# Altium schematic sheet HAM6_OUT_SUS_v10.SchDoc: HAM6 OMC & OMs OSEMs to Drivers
size C; Engineer: L. Sanchez; Organization: LIGO Laboratory; Address1: California Institute of Technology; Address2: Massachusetts Institute of Technology; DocumentNumber: D1002740; Revision: v10; SheetNumber: 4; SheetTotal: 8
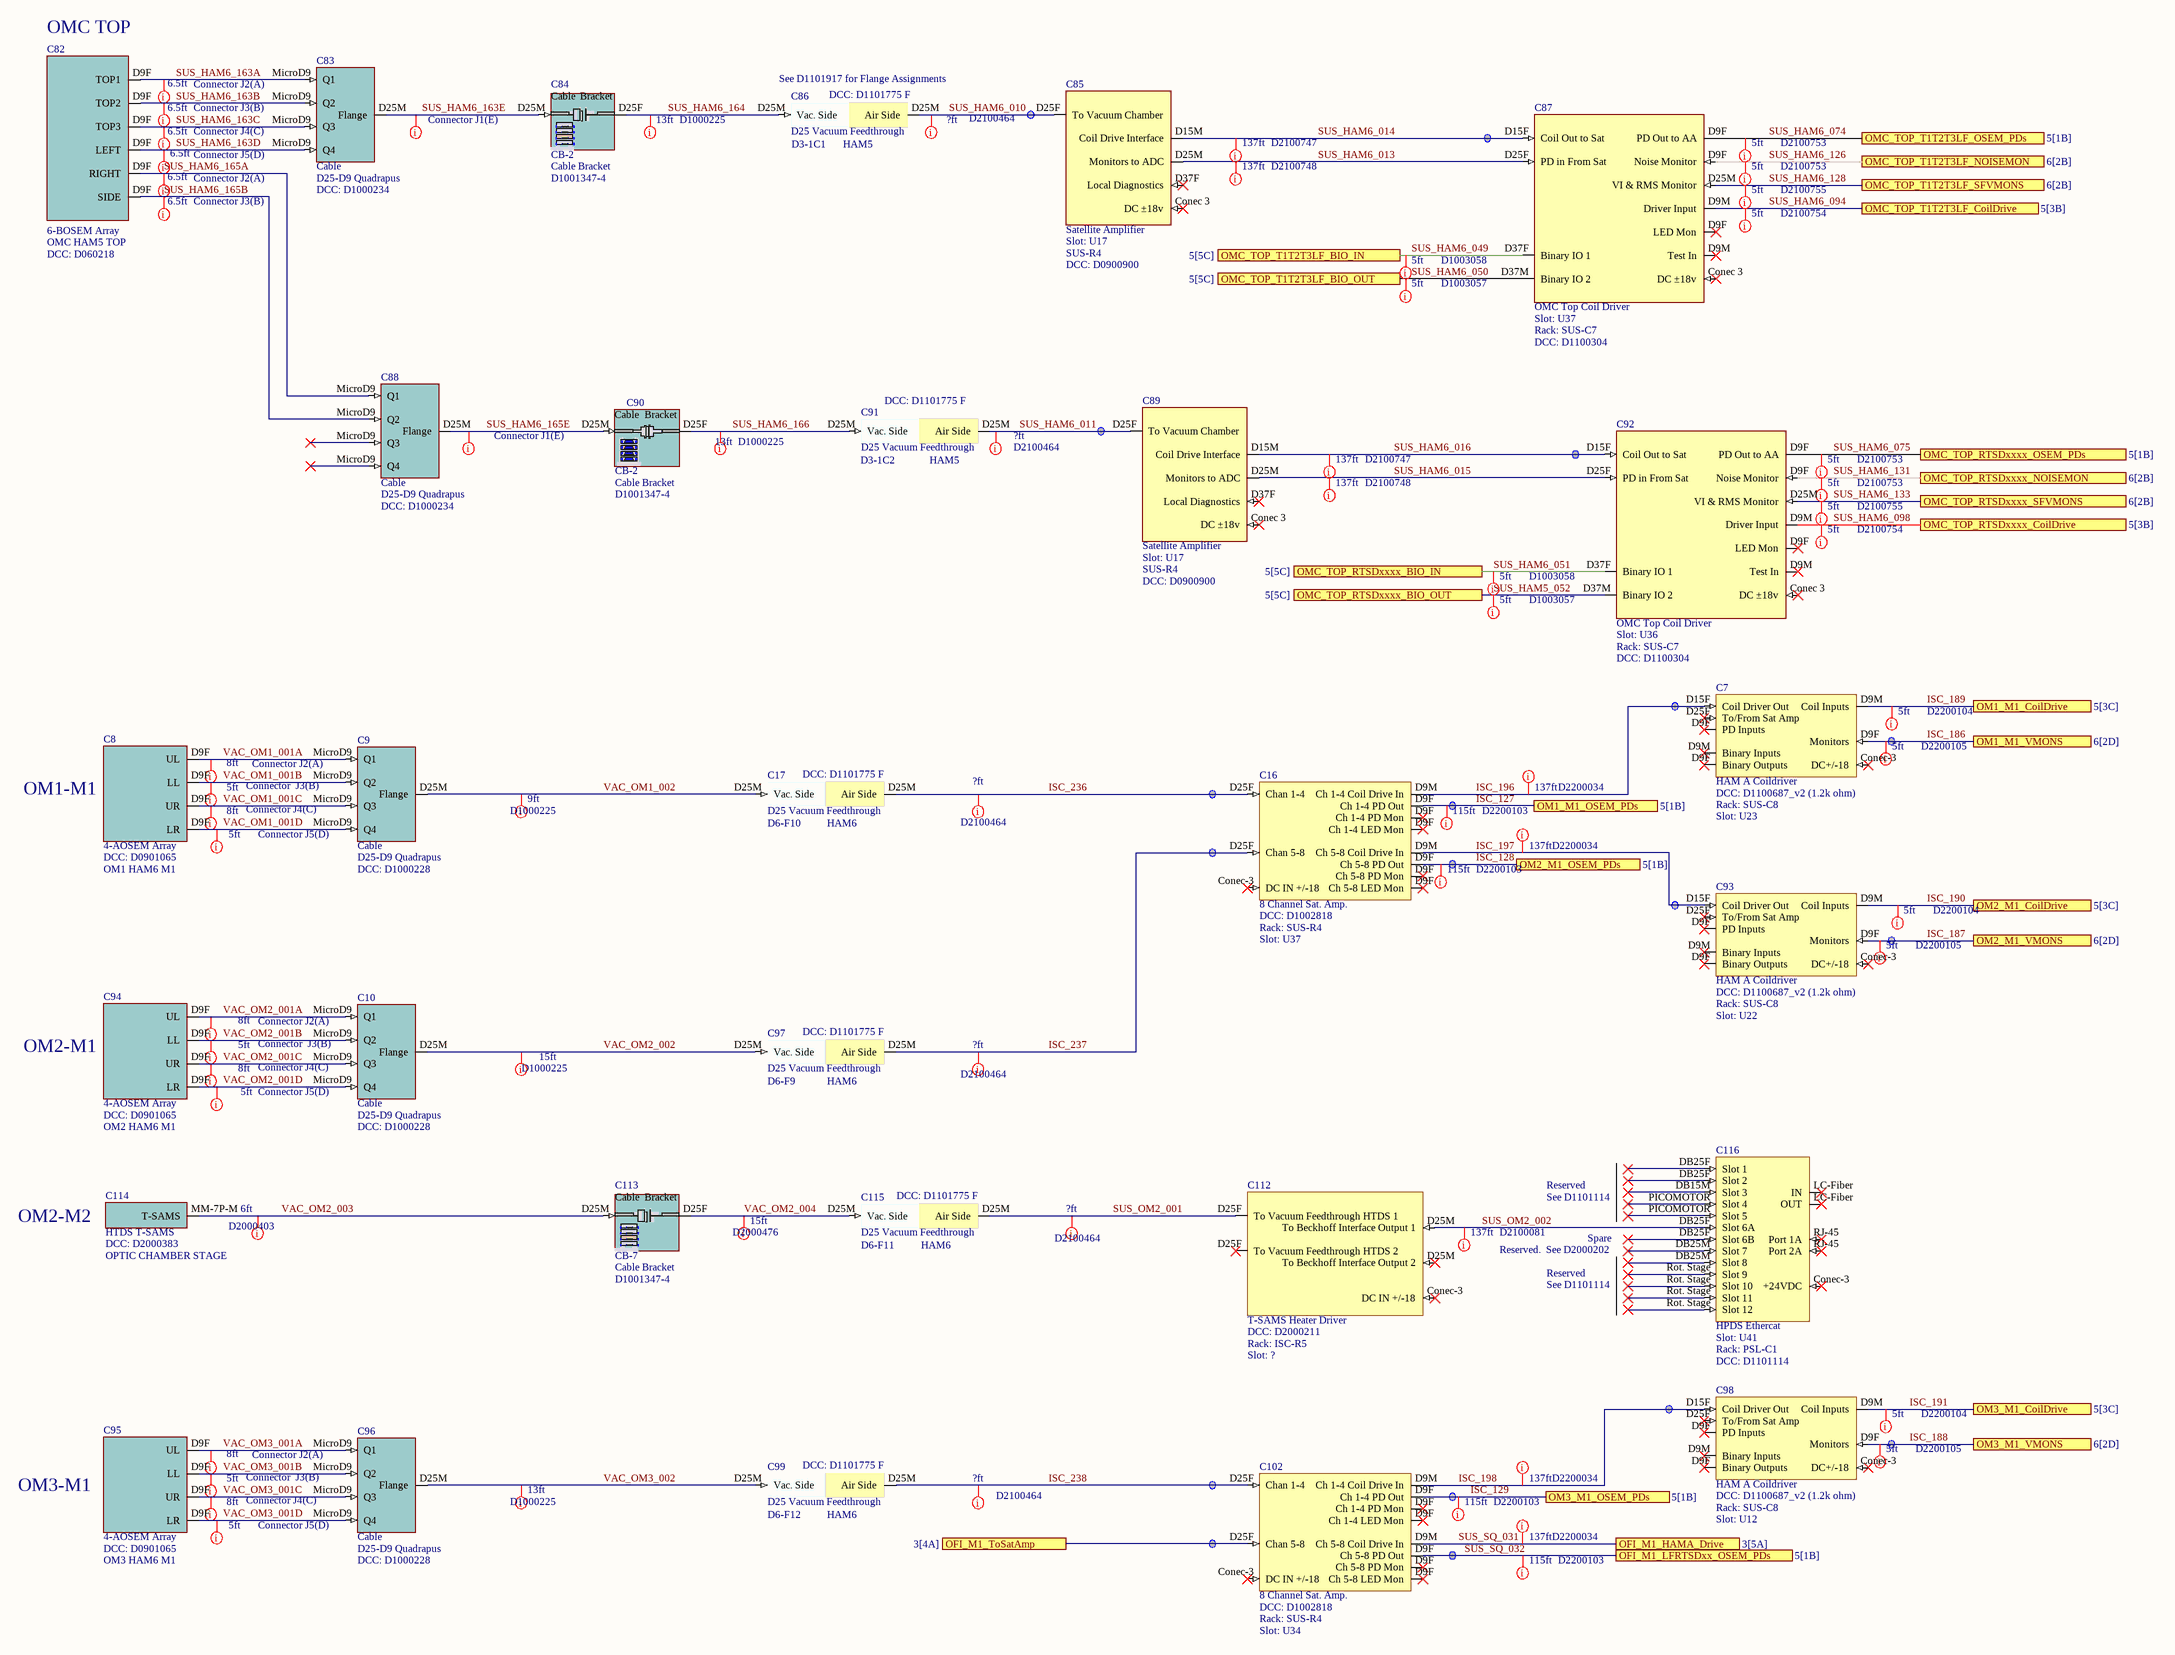
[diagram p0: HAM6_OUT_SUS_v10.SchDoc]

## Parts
C7  HAM A Coildriver  DCC: D1100687_v2 (1.2k ohm)  Rack: SUS-C8  Slot: U23
C8  4-AOSEM Array  DCC: D0901065  Parameter: OM1 HAM6 M1
C9  Cable  value D25-D9 Quadrapus  DCC: D1000228
C10  Cable  value D25-D9 Quadrapus  DCC: D1000228
C16  8 Channel Sat. Amp.  DCC: D1002818  Rack: SUS-R4  Slot: U37
C17  D25 Vacuum Feedthrough  DCC: D1101775 F  Feedthrough: D6-F10  Chamber: HAM6
C82  6-BOSEM Array  Parameter 1: OMC HAM5 TOP  DCC: D060218
C83  Cable  value D25-D9 Quadrapus  DCC: D1000234
C84  Slot: CB-2  DCC: D1001347-4  (hidden comment: Cable Bracket)
C85  Satellite Amplifier  Slot: U17  Rack: SUS-R4  DCC: D0900900
C86  D25 Vacuum Feedthrough  DCC: D1101775 F  Feedthrough: D3-1C1  Chamber: HAM5
C87  OMC Top Coil Driver  Slot: U37  Rack: SUS-C7  DCC: D1100304
C88  Cable  value D25-D9 Quadrapus  DCC: D1000234
C89  Satellite Amplifier  Slot: U17  Rack: SUS-R4  DCC: D0900900
C90  Slot: CB-2  DCC: D1001347-4  (hidden comment: Cable Bracket)
C91  D25 Vacuum Feedthrough  DCC: D1101775 F  Feedthrough: D3-1C2  Chamber: HAM5
C92  OMC Top Coil Driver  Slot: U36  Rack: SUS-C7  DCC: D1100304
C93  HAM A Coildriver  DCC: D1100687_v2 (1.2k ohm)  Rack: SUS-C8  Slot: U22
C94  4-AOSEM Array  DCC: D0901065  Parameter: OM2 HAM6 M1
C95  4-AOSEM Array  DCC: D0901065  Parameter: OM3 HAM6 M1
C96  Cable  value D25-D9 Quadrapus  DCC: D1000228
C97  D25 Vacuum Feedthrough  DCC: D1101775 F  Feedthrough: D6-F9  Chamber: HAM6
C98  HAM A Coildriver  DCC: D1100687_v2 (1.2k ohm)  Rack: SUS-C8  Slot: U12
C99  D25 Vacuum Feedthrough  DCC: D1101775 F  Feedthrough: D6-F12  Chamber: HAM6
C102  8 Channel Sat. Amp.  DCC: D1002818  Rack: SUS-R4  Slot: U34
C112  T-SAMS Heater Driver  DCC: D2000211  Rack: ISC-R5
C113  Slot: CB-7  DCC: D1001347-4  (hidden comment: Cable Bracket)
C114  HTDS T-SAMS  DCC: D2000383  Location: OPTIC CHAMBER STAGE
C115  D25 Vacuum Feedthrough  DCC: D1101775 F  Feedthrough: D6-F11  Chamber: HAM6
C116  HPDS Ethercat  Slot: U41  Rack: PSL-C1  DCC: D1101114

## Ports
OFI_M1_HAMA_Drive (see 3[5A]), OFI_M1_LFRTSDxx_OSEM_PDs (see 5[1B]), OFI_M1_ToSatAmp (see 3[4A]), OM1_M1_CoilDrive (see 5[3C]), OM1_M1_OSEM_PDs (see 5[1B]), OM1_M1_VMONS (see 6[2D]), OM2_M1_CoilDrive (see 5[3C]), OM2_M1_OSEM_PDs (see 5[1B]), OM2_M1_VMONS (see 6[2D]), OM3_M1_CoilDrive (see 5[3C]), OM3_M1_OSEM_PDs (see 5[1B]), OM3_M1_VMONS (see 6[2D]), OMC_TOP_RTSDxxxx_BIO_IN (see 5[5C]), OMC_TOP_RTSDxxxx_BIO_OUT (see 5[5C]), OMC_TOP_RTSDxxxx_CoilDrive (see 5[3B]), OMC_TOP_RTSDxxxx_NOISEMON (see 6[2B]), OMC_TOP_RTSDxxxx_OSEM_PDs (see 5[1B]), OMC_TOP_RTSDxxxx_SFVMONS (see 6[2B]), OMC_TOP_T1T2T3LF_BIO_IN (see 5[5C]), OMC_TOP_T1T2T3LF_BIO_OUT (see 5[5C]), OMC_TOP_T1T2T3LF_CoilDrive (see 5[3B]), OMC_TOP_T1T2T3LF_NOISEMON (see 6[2B]), OMC_TOP_T1T2T3LF_OSEM_PDs (see 5[1B]), OMC_TOP_T1T2T3LF_SFVMONS (see 6[2B])

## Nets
ISC_127: C16.D9F(Ch_1-4_PD_Out) ; port OM1_M1_OSEM_PDs
ISC_128: C16.D9F(Ch_5-8_PD_Out) ; port OM2_M1_OSEM_PDs
ISC_129: C102.D9F(Ch_1-4_PD_Out) ; port OM3_M1_OSEM_PDs
ISC_186: C7.D9F(PD_Inputs) ; port OM1_M1_VMONS
ISC_187: C93.D9F(PD_Inputs) ; port OM2_M1_VMONS
ISC_188: C98.D9F(PD_Inputs) ; port OM3_M1_VMONS
ISC_189: C7.D9M(Coil_Inputs) ; port OM1_M1_CoilDrive
ISC_190: C93.D9M(Coil_Inputs) ; port OM2_M1_CoilDrive
ISC_191: C98.D9M(Coil_Inputs) ; port OM3_M1_CoilDrive
ISC_196: C7.D15F(Coil_Driver_Out) C16.D9M(Ch_1-4_Coil_Drive_In)
ISC_197: C16.D9M(Ch_5-8_Coil_Drive_In) C93.D15F(Coil_Driver_Out)
ISC_198: C98.D15F(Coil_Driver_Out) C102.D9M(Ch_1-4_Coil_Drive_In)
ISC_236: C16.D25F(Chan_1-4) C17.D25M(Air_Side)
ISC_237: C16.D25F(Chan_5-8) C97.D25M(Air_Side)
ISC_238: C99.D25M(Air_Side) C102.D25F(Chan_1-4)
OFI_M1_ToSatAmp: C102.D25F(Chan_5-8) ; port OFI_M1_ToSatAmp
SUS_HAM5_052: C92.D37M(Binary_IO_2) ; port OMC_TOP_RTSDxxxx_BIO_OUT
SUS_HAM6_010: C85.D25F(To_Vacuum_Chamber) C86.D25M(Air_Side)
SUS_HAM6_011: C89.D25F(To_Vacuum_Chamber) C91.D25M(Air_Side)
SUS_HAM6_013: C85.D25M(Monitors_to_ADC) C87.D25F(PD_in_From_Sat)
SUS_HAM6_014: C85.D15M(Coil_Drive_Interface) C87.D15F(Coil_Out_to_Sat)
SUS_HAM6_015: C89.D25M(Monitors_to_ADC) C92.D25F(PD_in_From_Sat)
SUS_HAM6_016: C89.D15M(Coil_Drive_Interface) C92.D15F(Coil_Out_to_Sat)
SUS_HAM6_049: C87.D37F(Binary_IO_1) ; port OMC_TOP_T1T2T3LF_BIO_IN
SUS_HAM6_050: C87.D37M(Binary_IO_2) ; port OMC_TOP_T1T2T3LF_BIO_OUT
SUS_HAM6_051: C92.D37F(Binary_IO_1) ; port OMC_TOP_RTSDxxxx_BIO_IN
SUS_HAM6_074: C87.D9F(PD_Out_to_AA) ; port OMC_TOP_T1T2T3LF_OSEM_PDs
SUS_HAM6_075: C92.D9F(PD_Out_to_AA) ; port OMC_TOP_RTSDxxxx_OSEM_PDs
SUS_HAM6_094: C87.D9M(Test_In) ; port OMC_TOP_T1T2T3LF_CoilDrive
SUS_HAM6_098: C92.D9M(Test_In) ; port OMC_TOP_RTSDxxxx_CoilDrive
SUS_HAM6_126: C87.D9F(Noise_Monitor) ; port OMC_TOP_T1T2T3LF_NOISEMON
SUS_HAM6_128: C87.D25M(VI_&_RMS_Monitor) ; port OMC_TOP_T1T2T3LF_SFVMONS
SUS_HAM6_131: C92.D9F(Noise_Monitor) ; port OMC_TOP_RTSDxxxx_NOISEMON
SUS_HAM6_133: C92.D25M(VI_&_RMS_Monitor) ; port OMC_TOP_RTSDxxxx_SFVMONS
SUS_HAM6_163A: C82.D9F(TOP1) C83.MicroD9(Q1)
SUS_HAM6_163B: C82.D9F(TOP2) C83.MicroD9(Q2)
SUS_HAM6_163C: C82.D9F(TOP3) C83.MicroD9(Q3)
SUS_HAM6_163D: C82.D9F(LEFT) C83.MicroD9(Q4)
SUS_HAM6_163E: C83.D25M(Flange) C84.D25M
SUS_HAM6_164: C84.D25F C86.D25M(Vac._Side)
SUS_HAM6_165A: C82.D9F(RIGHT) C88.MicroD9(Q1)
SUS_HAM6_165B: C82.D9F(SIDE) C88.MicroD9(Q2)
SUS_HAM6_165E: C88.D25M(Flange) C90.D25M
SUS_HAM6_166: C90.D25F C91.D25M(Vac._Side)
SUS_OM2_001: C112.D25F(To_Vacuum_Feedthrough_HTDS_1) C115.D25M(Air_Side)
SUS_OM2_002: C112.D25M(To_Beckhoff_Interface_Output_1) C116.DB25F(Slot_1)
SUS_SQ_031: C102.D9M(Ch_5-8_Coil_Drive_In) ; port OFI_M1_HAMA_Drive
SUS_SQ_032: C102.D9F(Ch_5-8_PD_Out) ; port OFI_M1_LFRTSDxx_OSEM_PDs
VAC_OM1_001A: C8.D9F(UL) C9.MicroD9(Q1)
VAC_OM1_001B: C8.D9F(LL) C9.MicroD9(Q2)
VAC_OM1_001C: C8.D9F(UR) C9.MicroD9(Q3)
VAC_OM1_001D: C8.D9F(LR) C9.MicroD9(Q4)
VAC_OM1_002: C9.D25M(Flange) C17.D25M(Vac._Side)
VAC_OM2_001A: C10.MicroD9(Q1) C94.D9F(UL)
VAC_OM2_001B: C10.MicroD9(Q2) C94.D9F(LL)
VAC_OM2_001C: C10.MicroD9(Q3) C94.D9F(UR)
VAC_OM2_001D: C10.MicroD9(Q4) C94.D9F(LR)
VAC_OM2_002: C10.D25M(Flange) C97.D25M(Vac._Side)
VAC_OM2_003: C113.D25M C114.MM-7P-M(T-SAMS)
VAC_OM2_004: C113.D25F C115.D25M(Vac._Side)
VAC_OM3_001A: C95.D9F(UL) C96.MicroD9(Q1)
VAC_OM3_001B: C95.D9F(LL) C96.MicroD9(Q2)
VAC_OM3_001C: C95.D9F(UR) C96.MicroD9(Q3)
VAC_OM3_001D: C95.D9F(LR) C96.MicroD9(Q4)
VAC_OM3_002: C96.D25M(Flange) C99.D25M(Vac._Side)

Not connected (* = marked no-connect by the designer): C7 Conec-3(DC+/-18)* D25F(To/From_Sat_Amp)*; C16 Conec-3(DC_IN_+/-18)*; C85 Conec 3(DC_±18v)* D37F(Local_Diagnostics)*; C87 Conec 3(DC_±18v)*; C89 Conec 3(DC_±18v)* D37F(Local_Diagnostics)*; C92 Conec 3(DC_±18v)*; C93 Conec-3(DC+/-18)* D25F(To/From_Sat_Amp)*; C98 Conec-3(DC+/-18)* D25F(To/From_Sat_Amp)*; C102 Conec-3(DC_IN_+/-18)*; C112 Conec-3(DC_IN_+/-18)*; C116 Conec-3(+24VDC)* DB15M(Slot_3)* DB25M(Slot_8)* LC-Fiber(IN)* PICOMOTOR(Slot_4)* RJ-45(Port_1A)* Rot. Stage(Slot_9)*

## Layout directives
Length: 6.5ft; DCC: Connector J1(E): SUS_HAM6_163E, SUS_HAM6_165E
Length: 13ft; DCC: D1000225: SUS_HAM6_164, SUS_HAM6_166, VAC_OM3_002
Length: ?ft; DCC: D2100464: ISC_236, ISC_237, ISC_238, SUS_HAM6_010, SUS_HAM6_011, SUS_OM2_001
Length: 6.5ft; DCC: Connector J2(A): SUS_HAM6_163A, SUS_HAM6_165A
Length: 6.5ft; DCC: Connector J3(B): SUS_HAM6_163B, SUS_HAM6_165B
Length: 6.5ft; DCC: Connector J4(C): SUS_HAM6_163C
Length: 6.5ft; DCC: Connector J5(D): SUS_HAM6_163D
Length: 9ft; DCC: D1000225: VAC_OM1_002
Length: 5ft; DCC: Connector J5(D): VAC_OM1_001D, VAC_OM2_001D, VAC_OM3_001D
Length: 8ft; DCC: Connector J2(A): VAC_OM1_001A, VAC_OM2_001A, VAC_OM3_001A
Length: 5ft; DCC: Connector  J3(B): VAC_OM1_001B, VAC_OM2_001B, VAC_OM3_001B
Length: 8ft; DCC: Connector J4(C): VAC_OM1_001C, VAC_OM2_001C, VAC_OM3_001C
Length: 15ft; DCC: D1000225: VAC_OM2_002
Length: 6ft; DCC: D2000403: VAC_OM2_003
Length: 15ft; DCC: D2000476: VAC_OM2_004
Length: 5ft; DCC: D1003058: SUS_HAM6_049, SUS_HAM6_051
Length: 5ft; DCC: D1003057: SUS_HAM5_052, SUS_HAM6_050
Length: 137ft; DCC: D2100747: SUS_HAM6_014, SUS_HAM6_016
Length: 137ft; DCC: D2100748: SUS_HAM6_013, SUS_HAM6_015
Length: 5ft; DCC: D2100754: SUS_HAM6_094, SUS_HAM6_098
Length: 5ft; DCC: D2100755: SUS_HAM6_128, SUS_HAM6_133
Length: 5ft; DCC: D2100753: SUS_HAM6_074, SUS_HAM6_075, SUS_HAM6_126, SUS_HAM6_131
Length: 137ft; DCC: D2200034: ISC_196, ISC_197, ISC_198, SUS_SQ_031
Length: 115ft; DCC: D2200103: ISC_127, ISC_128, ISC_129, SUS_SQ_032
Length: 5ft; DCC: D2200105: ISC_186, ISC_187, ISC_188
Length: 5ft; DCC: D2200104: ISC_189, ISC_190, ISC_191
Length: 137ft; DCC: D2100081: SUS_OM2_002

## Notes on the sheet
- (near C82) OMC TOP
- (near C86) See D1101917 for Flange Assignments
- OM1-M1
- OM2-M1
- See D1101114
- Reserved
- OM2-M2
- Reserved.  See D2000202
- Spare
- OM3-M1

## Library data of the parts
C7 C93 C98 = HAM A Coildriver: Serial: Sxxxxxxx; System: ISC
C8 C94 C95 = 4-BOSEM Array: Rack: SUS-R?; Serial: Sxxxxxxx; Slot: U?; System: SUS
C9 C10 C83 C88 C96 = Flange: Rack: SUS-R?; Serial: Sxxxxxxx; Slot: U?; System: SUS
C16 C102 = 8 Channel Sat. Amp.: Serial: Sxxxxxxx; System: ISC
C17 C86 C91 C97 C99 C115 = VacFeedD25: Serial: Sxxxxxxx; System: ISC; Rack: R?; Slot: U?
C82 = 6-BOSEM Array HAM: Serial: Sxxxxxxx; System: SUS; Slot: U?; Rack: SUS-R?
C84 C113 = Cable Bracket 2 1-4: Rack: SUS-R?; Serial: Sxxxxxxx; System: SUS
C85 C89 = Satellite Amplifier: System: SUS; Serial: Sxxxxxxx
C87 C92 = OMC Top CD: System: SUS; Serial: Sxxxxxxx
C90 = Cable Bracket 3 1-4: Rack: SUS-R?; Serial: Sxxxxxxx; System: SUS
C112 = T-SAMS Heater Driver: Serial: Sxxxxxxx
C114 = HTDS T-SAMS: Heater and two thermistors; Rack: SUS-R?; Serial: Sxxxxxxx; Slot: U?; System: SUS
C116 = HPDS Ethercat: PSL - C1; System: MISC; Serial: Sxxxxxxx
